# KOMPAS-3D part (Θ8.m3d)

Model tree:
1. Эскиз:1
2. Операция выдавливания:1
     Расстояние 1 = 2
3. Скругление:1
     Радиус = 2
4. Эскиз:2
5. Вырезать элемент выдавливания:1
     Расстояние 1 = 10
